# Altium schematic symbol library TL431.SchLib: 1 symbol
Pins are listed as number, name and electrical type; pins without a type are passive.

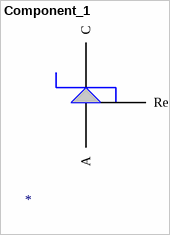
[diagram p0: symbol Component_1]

## Component_1
designator *
pins: 23 C, 24 A, 27 Ref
